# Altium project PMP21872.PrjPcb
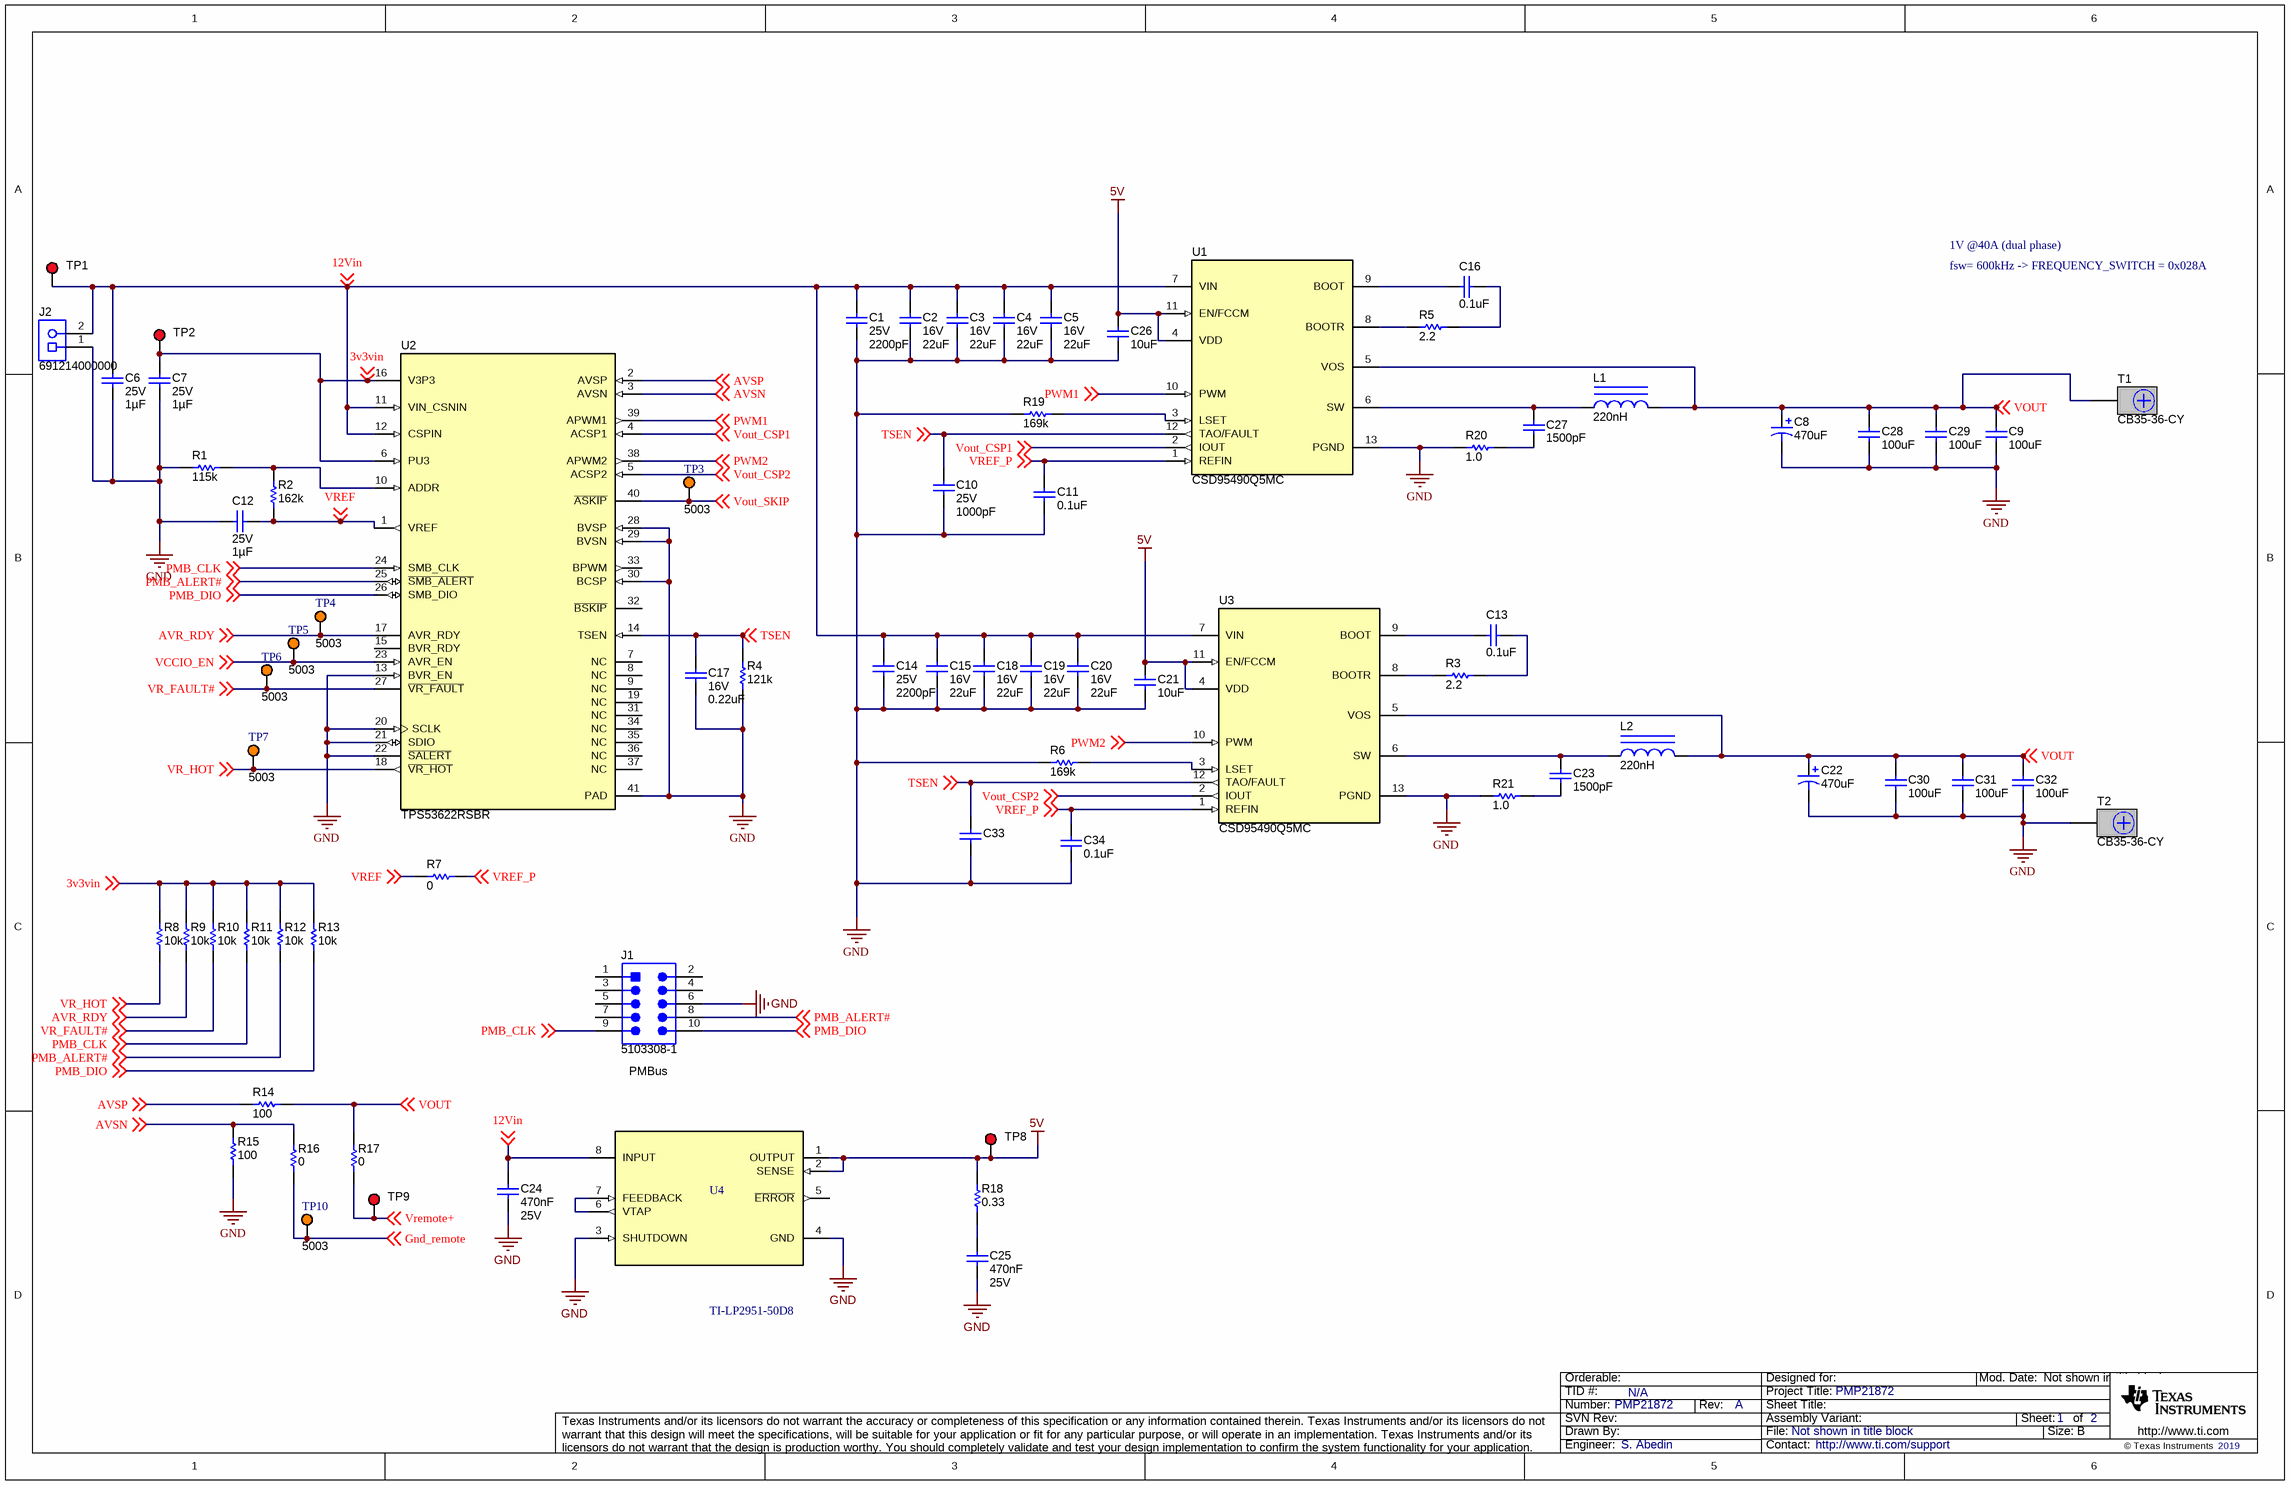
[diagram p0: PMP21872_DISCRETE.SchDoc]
CopyrightYear: 2019; PCB_Layout: V. Toledo; PCB_Rev: A; PRJ_Engineer: S. Abedin; PRJ_Number: PMP21872; PRJ_Title: PMP21872; SCH_Rev: A; TechSupport: http://www.ti.com/support; TID: N/A
1 sheet, 75 parts. Net scope: global (net labels, ports and power ports of the same name join across sheets).
Board file: PMP21872_REVA.PcbDoc

## Sheet PMP21872_DISCRETE.SchDoc
size 431 x 279 mm; Date: Not shown in title block; ApprovedBy: Not shown in title block; CheckedBy: Not shown in title block; Author: Not shown in title block; CompanyName: Not shown in title block; Engineer: Not shown in title block; Organization: Not shown in title block; Address1: Not shown in title block; Address2: Not shown in title block; Address3: Not shown in title block; Address4: Not shown in title block; DocumentNumber: 1; Revision: Use project parameter SCH_Rev; SheetNumber: 1; SheetTotal: 2; PageSetup: Record=PageOptions¦CenterHorizontal=True¦CenterVertical=True¦PrintScale=1.00¦XCorrection=1.00¦YCorrection=1.00¦PrintKind=0¦BorderSize=5000000¦LeftOffset=0¦BottomOffset=0¦Orientation=2¦PaperLength=1000¦PaperWidth=1000¦Scale=100¦PaperSource=15¦PrintQuality=600¦MediaType=1¦DitherType=10¦PaperKind=Letter¦PrintScaleMode=1

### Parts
C1  VDC_V: 25V  ValueDisplayed: 2200pF  [0402S]  (hidden comment: GRM155R71E222KA01D)
C2  VDC_V: 16V  ValueDisplayed: 22uF  [1206_180]  (hidden comment: GRM31CR61C226KE15L)
C3  VDC_V: 16V  ValueDisplayed: 22uF  [1206_180]  (hidden comment: GRM31CR61C226KE15L)
C4  VDC_V: 16V  ValueDisplayed: 22uF  [1206_180]  (hidden comment: GRM31CR61C226KE15L)
C5  VDC_V: 16V  ValueDisplayed: 22uF  [1206_180]  (hidden comment: GRM31CR61C226KE15L)
C6  VDC_V: 25V  ValueDisplayed: 1µF  [0603]  (hidden comment: CGJ3E1X7R1E105K080AC)
C7  VDC_V: 25V  ValueDisplayed: 1µF  [0603]  (hidden comment: CGJ3E1X7R1E105K080AC)
C8  ValueDisplayed: 470uF  [7343-20]  (hidden comment: Cap_Polarized)
C9  ValueDisplayed: 100uF  [1210_280]  (hidden comment: Capacitor)
C10  VDC_V: 25V  ValueDisplayed: 1000pF  [0402S]  (hidden comment: C0402C102J3GACTU)
C11  ValueDisplayed: 0.1uF  [0402S]  (hidden comment: Capacitor)
C12  VDC_V: 25V  ValueDisplayed: 1µF  [0603]  (hidden comment: CGJ3E1X7R1E105K080AC)
C13  ValueDisplayed: 0.1uF  [0402S]  (hidden comment: Capacitor)
C14  VDC_V: 25V  ValueDisplayed: 2200pF  [0402S]  (hidden comment: GRM155R71E222KA01D)
C15  VDC_V: 16V  ValueDisplayed: 22uF  [1206_180]  (hidden comment: GRM31CR61C226KE15L)
C16  ValueDisplayed: 0.1uF  [0402S]  (hidden comment: Capacitor)
C17  VDC_V: 16V  ValueDisplayed: 0.22uF  [0402S]  (hidden comment: GRM155R71C224KA12D)
C18  VDC_V: 16V  ValueDisplayed: 22uF  [1206_180]  (hidden comment: GRM31CR61C226KE15L)
C19  VDC_V: 16V  ValueDisplayed: 22uF  [1206_180]  (hidden comment: GRM31CR61C226KE15L)
C20  VDC_V: 16V  ValueDisplayed: 22uF  [1206_180]  (hidden comment: GRM31CR61C226KE15L)
C21  ValueDisplayed: 10uF  [0603L]  (hidden comment: Capacitor)
C22  ValueDisplayed: 470uF  [7343-20]  (hidden comment: Cap_Polarized)
C23  ValueDisplayed: 1500pF  [0805_HV]  (hidden comment: Capacitor)
C24  Cap_F: 470nF  VDC_V: 25V  [0603]  (hidden comment: C1608X7R1E474K080AE)
C25  Cap_F: 470nF  VDC_V: 25V  [0603]  (hidden comment: C1608X7R1E474K080AE)
C26  ValueDisplayed: 10uF  [0603L]  (hidden comment: Capacitor)
C27  ValueDisplayed: 1500pF  [0805_HV]  (hidden comment: Capacitor)
C28  ValueDisplayed: 100uF  [1210_280]  (hidden comment: Capacitor)
C29  ValueDisplayed: 100uF  [1210_280]  (hidden comment: Capacitor)
C30  ValueDisplayed: 100uF  [1210_280]  (hidden comment: Capacitor)
C31  ValueDisplayed: 100uF  [1210_280]  (hidden comment: Capacitor)
C32  ValueDisplayed: 100uF  [1210_280]  (hidden comment: Capacitor)
C33  C1005C0G1E102J  [0402S]  (value not drawn)
C34  ValueDisplayed: 0.1uF  [0402S]  (hidden comment: Capacitor)
J1  5103308-1  [CONN_5103308-1]
J2  691214000000  [Wurth_691214310002]
L1  ValueDisplayed: 220nH  [CMLE064T_-24]  (hidden comment: CMLE064T-R22MS0R987)
L2  ValueDisplayed: 220nH  [CMLE064T_-24]  (hidden comment: CMLE064T-R22MS0R987)
R1  ValueDisplayed: 115k  [0402S]  (hidden comment: RC0402FR-07115KL)
R2  ValueDisplayed: 162k  [0402S]  (hidden comment: CRCW0402162KFKED)
R3  value 2.2  [0402S]  (hidden comment: Resistor)
R4  ValueDisplayed: 121k  [0402S]  (hidden comment: CRCW0402121KFKED)
R5  value 2.2  [0402S]  (hidden comment: Resistor)
R6  ValueDisplayed: 169k  [0402S]  (hidden comment: CRCW0402169KFKED)
R7  ValueDisplayed: 0  [0402S]  (hidden comment: Resistor)
R8  ValueDisplayed: 10k  [0402S]  (hidden comment: ERJ-2GEJ103X)
R9  ValueDisplayed: 10k  [0402S]  (hidden comment: ERJ-2GEJ103X)
R10  ValueDisplayed: 10k  [0402S]  (hidden comment: ERJ-2GEJ103X)
R11  ValueDisplayed: 10k  [0402S]  (hidden comment: ERJ-2GEJ103X)
R12  ValueDisplayed: 10k  [0402S]  (hidden comment: ERJ-2GEJ103X)
R13  ValueDisplayed: 10k  [0402S]  (hidden comment: ERJ-2GEJ103X)
R14  ValueDisplayed: 100  [0402S]  (hidden comment: ERJ-2GEJ101X)
R15  ValueDisplayed: 100  [0402S]  (hidden comment: ERJ-2GEJ101X)
R16  ValueDisplayed: 0  [0402S]  (hidden comment: Resistor)
R17  ValueDisplayed: 0  [0402S]  (hidden comment: Resistor)
R18  ValueDisplayed: 0.33  [0603]  (hidden comment: ERJ-3RQFR33V)
R19  ValueDisplayed: 169k  [0402S]  (hidden comment: CRCW0402169KFKED)
R20  value 1.0  [1206]  (hidden comment: Resistor)
R21  value 1.0  [1206]  (hidden comment: Resistor)
T1  CB35-36-CY  [CB35-36-CY]
T2  CB35-36-CY  [CB35-36-CY]
TP1  5000  [Keystone5000]  (value not drawn)
TP2  5000  [Keystone5000]  (value not drawn)
TP3  5003  [Keystone5003]
TP4  5003  [Keystone5003]
TP5  5003  [Keystone5003]
TP6  5003  [Keystone5003]
TP7  5003  [Keystone5003]
TP8  5000  [Keystone5000]  (value not drawn)
TP9  5000  [Keystone5000]  (value not drawn)
TP10  5003  [Keystone5003]
U1  CSD95490Q5MC  [DMC0012A]
U2  TPS53622RSBR  [RSB0040E]
U3  CSD95490Q5MC  [DMC0012A]
U4  TI-LP2951-50D8  [D0008A_N]

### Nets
5V: C21.1 C26.1 R18.2 TP8.1 U1.4(VDD) U1.11(EN/FCCM) U3.4(VDD) U3.11(EN/FCCM) U4.1(OUTPUT) U4.2(SENSE)
GND: C1.2 C2.2 C3.2 C4.2 C5.2 C6.2 C7.2 C8.2(-) C9.2 C10.2 C11.2 C12.2 C14.2 C15.2 C17.2 C18.2 C19.2 C20.2 C21.2 C22.2(-) C24.2 C25.2 C26.2 C28.2 C29.2 C30.2 C31.2 C32.2 C33.2 C34.2 J1.6 J2.1 R1.1 R4.1 R6.1 R15.1 R19.1 R20.2 R21.2 T2.1 U1.13(PGND) U2.13(BVR_EN) U2.20(SCLK) U2.21(SDIO) U2.22(~{SALERT}) U2.28(BVSP) U2.29(BVSN) U2.30(BCSP) U2.41(PAD) U3.13(PGND) U4.3(SHUTDOWN) U4.4(GND)
3v3vin: C7.1 R8.2 R9.2 R10.2 R11.2 R12.2 R13.2 TP2.1 U2.6(PU3) U2.16(V3P3) ; off-sheet 3v3vin
12Vin: C1.1 C2.1 C3.1 C4.1 C5.1 C6.1 C14.1 C15.1 C18.1 C19.1 C20.1 C24.1 J2.2 TP1.1 U1.7(VIN) U2.11(VIN_CSNIN) U2.12(CSPIN) U3.7(VIN) U4.8(INPUT) ; off-sheet 12Vin
AVR_RDY: R9.1 TP4.1 U2.17(AVR_RDY) ; off-sheet AVR_RDY
AVSN: R15.2 R16.1 U2.3(AVSN) ; off-sheet AVSN
AVSP: R14.2 U2.2(AVSP) ; off-sheet AVSP
Gnd_remote: R16.2 TP10.1 ; off-sheet Gnd_remote
PMB_ALERT#: J1.8 R12.1 U2.25(~{SMB_ALERT}) ; off-sheet PMB_ALERT#
PMB_CLK: J1.9 R11.1 U2.24(SMB_CLK) ; off-sheet PMB_CLK
PMB_DIO: J1.10 R13.1 U2.26(SMB_DIO) ; off-sheet PMB_DIO
PWM1: U1.10(PWM) U2.39(APWM1) ; off-sheet PWM1
PWM2: U2.38(APWM2) U3.10(PWM) ; off-sheet PWM2
TSEN: C10.1 C17.1 C33.1 R4.2 U1.12(TAO/FAULT) U2.14(TSEN) U3.12(TAO/FAULT) ; off-sheet TSEN
VCCIO_EN: TP5.1 U2.23(AVR_EN) ; off-sheet VCCIO_EN
VOUT: C8.1(+) C9.1 C22.1(+) C28.1 C29.1 C30.1 C31.1 C32.1 L1.2 L2.2 R14.1 R17.1 T1.1 U1.5(VOS) U3.5(VOS) ; off-sheet VOUT
Vout_CSP1: U1.2(IOUT) U2.4(ACSP1) ; off-sheet Vout_CSP1
Vout_CSP2: U2.5(ACSP2) U3.2(IOUT) ; off-sheet Vout_CSP2
Vout_SKIP: TP3.1 U2.40(~{ASKIP}) ; off-sheet Vout_SKIP
VR_FAULT#: R10.1 TP6.1 U2.27(~{VR_FAULT}) ; off-sheet VR_FAULT#
VR_HOT: R8.1 TP7.1 U2.18(~{VR_HOT}) ; off-sheet VR_HOT
VREF: C12.1 R2.1 R7.1 U2.1(VREF) ; off-sheet VREF
VREF_P: C11.1 C34.1 R7.2 U1.1(REFIN) U3.1(REFIN) ; off-sheet VREF_P
Vremote+: R17.2 TP9.1 ; off-sheet Vremote+
NetC13_1: C13.1 U3.9(BOOT)
NetC13_2: C13.2 R3.1
NetC16_1: C16.1 U1.9(BOOT)
NetC16_2: C16.2 R5.1
NetC23_1: C23.1 L2.1 U3.6(SW)
NetC23_2: C23.2 R21.1
NetC25_1: C25.1 R18.1
NetC27_1: C27.1 L1.1 U1.6(SW)
NetC27_2: C27.2 R20.1
NetR1_2: R1.2 R2.2 U2.10(ADDR)
NetR3_2: R3.2 U3.8(BOOTR)
NetR5_2: R5.2 U1.8(BOOTR)
NetR6_2: R6.2 U3.3(LSET)
NetR19_2: R19.2 U1.3(LSET)
NetU4_6: U4.6(VTAP) U4.7(FEEDBACK)

Not connected (* = marked no-connect by the designer): J1 1 2 3 4 5 7; U2 7(NC) 8(NC) 9(NC) 15(BVR_RDY) 19(NC) 31(NC) 32(~{BSKIP}) 33(BPWM) 34(NC) 35(NC) 36(NC) 37(NC); U4 5(~{ERROR})

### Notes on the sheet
- 1V @40A (dual phase)
- fsw= 600kHz -> FREQUENCY_SWITCH = 0x028A
- (near J1) PMBus

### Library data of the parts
C1 C14 = CMP-0006663-2: CAP, CERM, 2200 pF, 25 V, +/- 10%, X7R, 0402; Manufacturer: MuRata; TaMin_C: -55°C; Polarized: N; SizeAreaWB_mm2: 3; Value1: Unknown; U/M: EA; Value: 2200pF; TaMax_C: 125°C; SizeZ_mm: 0.6; SizeX_mm: 1; SizeY_mm: 0.5; Cap_Case: 0402; Cap_F: 2.2nF; AEC Category: Q200
C2-C5 C15 C18-C20 = CMP-0008946-2: CAP, CERM, 22 uF, 16 V, +/- 10%, X5R, 1206; Manufacturer: MuRata; TaMin_C: -55°C; Polarized: N; SizeAreaWB_mm2: 10.92; Value1: Unknown; U/M: EA; Value: 22uF; TaMax_C: 85°C; SizeZ_mm: 1.8; SizeX_mm: 3.2; SizeY_mm: 1.6; Cap_Case: 1206; SizeArea_mm2: 5.12; Cap_F: 22µF; AEC Category: Q200
C6 C7 C12 = CMP-0083856-1: CAP, CERM, 1 µF, 25 V,+/- 10%, X7R, 0603; Manufacturer: TDK; TaMin_C: -55°C; Polarized: N; SizeAreaWB_mm2: 4.68; U/M: EA; Value: 1uF; TaMax_C: 125°C; SizeZ_mm: 1; SizeX_mm: 1.6; SizeY_mm: 0.8; SizeArea_mm2: 1.28; AEC Category: Q200
C8 C22 = CMP-0012257-4: CAP, Aluminum Polymer, 470 uF, 2.5 V, +/- 20%, 4.5 ohm, 7343-20, SMD; PartNumber: EEFSX0E471E4; Manufacturer: Panasonic; Polarized: Y; CompType: Capacitor; Value: 470uF; Cap_F: 470µF; Value1: 4.5 ohm; VDC_V: 2.5V; ESR_ohm: 4.5; IRMS_A: 3A; TaMin_C: -40°C; TaMax_C: 105°C; AEC Category: Q200; AEC Qualified: N; SizeAreaWB_mm2: 58.59; SizeArea_mm2: 31.39; SizeX_mm: 7.3; SizeY_mm: 4.3; SizeZ_mm: 2.0
C9 C28-C32 = CMP-0009083-2: CAP, CERM, 100 uF, 6.3 V, +/- 20%, X5R, 1210; PartNumber: C1210C107M9PACTU; Manufacturer: Kemet; Polarized: N; Value: 100uF; U/M: EA; Cap_F: 100µF; Value1: Unknown; VDC_V: 6.3V; TaMin_C: -55°C; TaMax_C: 85°C; Cap_Case: 1210; SizeArea_mm2: 8; SizeAreaWB_mm2: 14.7; SizeX_mm: 3.2; SizeY_mm: 2.5; SizeZ_mm: 2.8; AEC Category: Q200
C10 = CMP-0081059-1: CAP, CERM, 1000 pF, 25 V,+/- 5%, C0G/NP0, 0402; Manufacturer: Kemet; TaMin_C: -55°C; Polarized: N; Green_Lifecycle: Active; SizeAreaWB_mm2: 3; Green_REACh: Passed; U/M: EA; Value: 1000pF; TaMax_C: 125°C; SizeZ_mm: 0.6; SizeX_mm: 1; SizeY_mm: 0.5; Cap_Case: 0402; Cap_F: 1nF; AEC Category: Q200
C11 C34 = CMP-0006591-2: CAP, CERM, 0.1 uF, 16 V, +/- 10%, X5R, 0402; PartNumber: GRM155R61C104KA88D; Manufacturer: MuRata; Polarized: N; Value: 0.1uF; U/M: EA; Cap_F: 100nF; Value1: Unknown; VDC_V: 16V; TaMin_C: -55°C; TaMax_C: 85°C; Cap_Case: 0402; SizeArea_mm2: 0.5; SizeAreaWB_mm2: 3; SizeX_mm: 1; SizeZ_mm: 0.6; AEC Category: Q200
C13 C16 = CMP-0006607-2: CAP, CERM, 0.1 uF, 25 V, +/- 10%, X5R, 0402; PartNumber: GRM155R61E104KA87D; Manufacturer: MuRata; Polarized: N; Value: 0.1uF; U/M: EA; Cap_F: 100nF; Value1: Unknown; VDC_V: 25V; TaMin_C: -55°C; TaMax_C: 85°C; Cap_Case: 0402; SizeArea_mm2: 0.5; SizeAreaWB_mm2: 3; SizeX_mm: 1; SizeZ_mm: 0.6; AEC Category: Q200
C17 = CMP-0006648-2: CAP, CERM, 0.22 uF, 16 V, +/- 10%, X7R, 0402; Manufacturer: MuRata; TaMin_C: -55°C; Polarized: N; SizeAreaWB_mm2: 3; Value1: Unknown; U/M: EA; Value: 0.22uF; TaMax_C: 125°C; SizeZ_mm: 0.6; SizeX_mm: 1; SizeY_mm: 0.5; Cap_Case: 0402; Cap_F: 220nF; AEC Category: Q200
C21 C26 = CMP-0006872-5: CAP, CERM, 10 uF, 6.3 V, +/- 20%, X5R, 0603; PartNumber: C0603C106M9PACTU; Manufacturer: Kemet; Polarized: N; Value: 10uF; U/M: EA; Cap_F: 10µF; ESR_ohm: 4m; Value1: 0.004 ohm; VDC_V: 6.3V; IRMS_A: 8.9A; TaMin_C: -55°C; TaMax_C: 85°C; Cap_Case: 0603; SizeArea_mm2: 1.28; SizeAreaWB_mm2: 4.68; SizeX_mm: 1.6; SizeY_mm: 0.8; SizeZ_mm: 1; AEC Category: Q200
C23 C27 = CMP-0007545-2: CAP, CERM, 1500 pF, 100 V, +/- 10%, X7R, 0805; PartNumber: 08051C152KAT2A; Manufacturer: AVX; Polarized: N; Value: 1500pF; U/M: EA; Cap_F: 1.5nF; ESR_ohm: 0.229; Value1: 0.229 ohm; VDC_V: 100V; TaMin_C: -55°C; TaMax_C: 125°C; Cap_Case: 0805; SizeArea_mm2: 2.5; SizeAreaWB_mm2: 6.75; SizeX_mm: 2; SizeY_mm: 1.25; SizeZ_mm: 1.45; AEC Category: Q200
C24 C25 = CMP-0750175-1: CAP, CERM, 0.47 µF, 25 V,+/- 10%, X7R, 0603; Manufacturer: TDK; AEC Qualified: N; TaMax_C: 125°C; U/M: EA; AEC Category: Q200; Value: 0.47uF; SizeX_mm: 1.6; SizeAreaWB_mm2: 4.68; SizeZ_mm: 1; SizeY_mm: 0.8; SizeArea_mm2: 1.28; ValueDisplayed: 0.47µF; TaMin_C: -55°C
C33 = C1005C0G1E102J: CAP, CERM, 1000 pF, 25 V, +/- 5%, C0G/NP0, 0402; Manufacturer: TDK; Polarized: N; CompType: Capacitor; Value: 1000pF; U/M: EA; Cap_F: 0.000000001; Tolerance_%: 5; Value1: Unknown; VDC_V: 25; Value2: 25V; TaMin_C: -55; TaMax_C: 125; Cap_Case: 0402
J1 = CMP-0054834-2: Header (shrouded), 100mil, 5x2, Gold, TH; Manufacturer: TE Connectivity; Green_Lifecycle: Active; Green_REACh: Passed
J2 = CMP-0054822-1: Terminal Block, 2x1, 3.81mm, 24-16 AWG, 10A, 300VAC, TH; Manufacturer: Wurth Elektronik; CT: TRUE; Green_REACh: Passed; CNHeader: FALSE; Green_Lifecycle: Active
L1 L2 = CMP-0059637-1: Inductor, 220 nH, 28.5 A, 0.00098 ohm, SMD; Manufacturer: Cyntec; Isat: 28.5A @ 30% inductance drop; Irms: 32A @ 40C rise; Green_Lifecycle: Not Set; SizeAreaWB_mm2: 84.48; DCR_ohm: 980µ; Green_REACh: Incomplete; Value: 220nH; Imax_A: 28.5A; SizeZ_mm: 4; SizeX_mm: 6.8; SizeY_mm: 7.6; SizeArea_mm2: 51.68; AEC Qualified: N; AEC Category: Q200
R1 = CMP-0077551-1: RES, 115 k, 1%, 0.063 W, 0402; Manufacturer: Yageo America; SizeArea_mm2: 0.5; AEC Qualified: N; AEC Category: Q200; Value: 115k; SizeZ_mm: 0.6; EIA_Code: E96; TempCo: 100 ppm/C; Power_W: 63mW; VDC_V: 50V; Value2: 0.063W; U/M: EA; SizeX_mm: 1.0
R2 = CMP-0026034-3: RES, 162 k, 1%, 0.063 W, AEC-Q200 Grade 0, 0402; Manufacturer: Vishay-Dale; Power_W: 63mW; TempCo: 100 ppm/C; Value: 162k; EIA_Code: E96; SizeX_mm: 1; SizeY_mm: 0.5; SizeZ_mm: 0.6; Value2: 0.063W; AEC Qualified: Y; VDC_V: 50V; AEC Category: Q200; AEC Grade: 0
R3 R5 = CMP-0026898-3: RES, 2.2, 5%, 0.063 W, AEC-Q200 Grade 0, 0402; PartNumber: CRCW04022R20JNED; Manufacturer: Vishay-Dale; Value_Code: 2R20; Power_W: 63mW; Value2: 0.063W; VDC_V: 50V; TempCo: 200 ppm/C; EIA_Code: E24; SizeArea_mm2: 0.5; SizeX_mm: 1; SizeZ_mm: 0.6; AEC Category: Q200; AEC Qualified: Y; AEC Grade: 0
R4 = CMP-0025984-3: RES, 121 k, 1%, 0.063 W, AEC-Q200 Grade 0, 0402; Manufacturer: Vishay-Dale; Power_W: 63mW; TempCo: 100 ppm/C; Value: 121k; EIA_Code: E96; SizeX_mm: 1; SizeY_mm: 0.5; SizeZ_mm: 0.6; Value2: 0.063W; AEC Qualified: Y; VDC_V: 50V; AEC Category: Q200; AEC Grade: 0
R6 R19 = CMP-0026038-3: RES, 169 k, 1%, 0.063 W, AEC-Q200 Grade 0, 0402; Manufacturer: Vishay-Dale; Power_W: 63mW; TempCo: 100 ppm/C; Value: 169k; EIA_Code: E96; SizeX_mm: 1; SizeY_mm: 0.5; SizeZ_mm: 0.6; Value2: 0.063W; AEC Qualified: Y; VDC_V: 50V; AEC Category: Q200; AEC Grade: 0
R7 R16 R17 = CMP-0026822-3: RES, 0, 5%, 0.063 W, AEC-Q200 Grade 0, 0402; PartNumber: CRCW04020000Z0ED; Manufacturer: Vishay-Dale; Value: 0; Value_Code: 0000; Power_W: 63mW; Value2: 0.063W; VDC_V: 50V; TempCo: 200 ppm/C; EIA_Code: E24; SizeArea_mm2: 0.5; SizeX_mm: 1; SizeZ_mm: 0.6; AEC Category: Q200; AEC Qualified: Y
R8-R13 = CMP-0026994-4: RES, 10 k, 5%, 0.1 W, AEC-Q200 Grade 0, 0402; Manufacturer: Panasonic; Power_W: 100mW; TempCo: 200 ppm/C; Value_Code: 10k0; U/M: EA; Value: 10k; EIA_Code: E24; SizeX_mm: 1; SizeY_mm: 0.5; SizeZ_mm: 0.6; Value2: 0.1W; AEC Qualified: Y; VDC_V: 50V; AEC Grade: 0; AEC Category: Q200
R14 R15 = CMP-0026993-2: RES, 100, 5%, 0.1 W, AEC-Q200 Grade 0, 0402; Manufacturer: Panasonic; Power_W: 100mW; TempCo: 200 ppm/C; Value_Code: 100R; U/M: EA; Value: 100; EIA_Code: E24; SizeX_mm: 1; SizeY_mm: 0.5; SizeZ_mm: 0.6; Value2: 0.1W; AEC Qualified: Y; AEC Grade: 0; AEC Category: Q200
R18 = CMP-0022714-1: RES, 0.33, 1%, 0.1 W, 0603; Manufacturer: Panasonic; Power_W: 100mW; TempCo: 300 ppm/C; Value_Code: R330; U/M: EA; Value: 0.33; EIA_Code: E96; SizeX_mm: 1.6; SizeY_mm: 0.8; SizeZ_mm: 1; Value2: 0.1W; SizeArea_mm2: 1.28; AEC Category: Q200
R20 R21 = CMP-0018745-2: RES, 1.0, 5%, 0.5 W, 1206; PartNumber: CRM1206-JW-1R0ELF; Manufacturer: Bourns; Res_ohm: 1; Value_Code: 1R00; Power_W: 500mW; Value2: 0.5W; VDC_V: 1V; TempCo: 150 ppm/C; EIA_Code: E24; U/M: EA; SizeArea_mm2: 5.12; SizeX_mm: 3.2; SizeY_mm: 1.6; SizeZ_mm: 1.35; AEC Category: Q200
T1 T2 = CMP-0055442-1: Terminal 50A Lug; Manufacturer: Panduit; CNHeader: FALSE; Green_Lifecycle: Not Set; Cert_CULUS: Y; Green_REACh: Incomplete; Voltage_V: 600V; CompType: Screw Terminal; ContactFinish: Copper
TP1 TP2 TP8 TP9 = CMP-0055137-1: Test Point, Miniature, Red, TH; Manufacturer: Keystone; ContactFinish: Silver; Green_Lifecycle: Active; Green_REACh: Passed; CNHeader: FALSE; CT: TRUE
TP3-TP7 TP10 = CMP-0055140-1: Test Point, Miniature, Orange, TH; Manufacturer: Keystone; CNHeader: FALSE; Green_Lifecycle: Active; Green_REACh: Passed; ContactFinish: Silver; CT: TRUE
U1 U3 = CMP-0013339-3: Synchronous Buck NexFET Power Stage, DMC0012A (VSON-CLIP-12); Manufacturer: Texas Instruments; Alternate PartNumber: CSD95490Q5MCT; Alternate Manufacturer: None; SizeX_mm: 5; SizeY_mm: 6; CompType: IC; SizeZ_mm: 1.05; SizeArea_mm2: 30; SizeAreaWB_mm2: 56; U/M: EA
U2 = CMP-0077545-2: Dual-Channel (1-Phase + 1-Phase) or (2-Phase + 0-Phase) D-CAP+Step-Down Multiphase Controller with NVM and PMBus for VR13 Server V CCIO + V MCP, RSB0040E (WQFN-40); Manufacturer: Texas Instruments; Alternate PartNumber: TPS53622RSBT; Alternate Manufacturer: None; SizeAreaWB_mm2: 49; SizeArea_mm2: 25; SizeZ_mm: 0.8; SizeY_mm: 5; CompType: IC; AEC Category: Q200; AEC Qualified: N
U4 = CMP-0037104-1: Fixed Regulator with 1 to 30 V Input and 1.2 to 30 V Output, -40 to 125 degC, 8-Pin SOIC (D), Green (RoHS & no Sb/Br); PartNumber: LP2951-50DR; Manufacturer: Texas Instruments; Iout(Max)(A): 0.1; Iq(Typ)(mA): 0.075; Vin(Max)(V): 30; Vin(Min)(V): 1; Vout(Min)(V): 1.2

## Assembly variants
001: not fitted C10 C23 C27 C33 R20 R21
